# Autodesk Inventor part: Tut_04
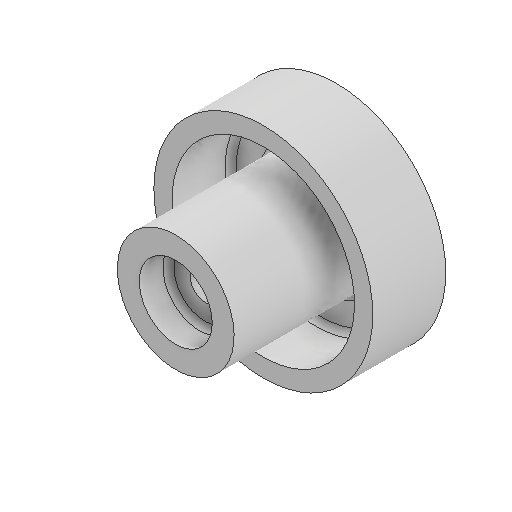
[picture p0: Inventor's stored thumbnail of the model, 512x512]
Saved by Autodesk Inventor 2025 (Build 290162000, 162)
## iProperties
Created: 2019-02
Part Number: Tut_04
Material: Generic
Document SubType Name: Modeling
Designer: LENOVO-CADCIM
Density: 1 g/cm^3
Appearance: Default
Author: LENOVO-CADCIM
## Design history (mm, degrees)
revolve "Revolution1" stored, may be unused: angle "d31" = 90 deg
body "Solid1"
sketch "Sketch1"
  geometry: L1 (0, 0)-(0, 22); L2 (0, 22)-(4, 22); L3 (4, 22)-(4, 36); L4 (4, 36)-(8.5, 36); L5 (10, 37.5)-(10, 44); L6 (10, 44)-(16, 44); L7 (16, 44)-(16, 5.5); L8 (17.5, 4)-(23.5, 4); L9 (25, 5.5)-(25, 20); L10 (25, 20)-(30, 20); L11 (30, 20)-(30, 0); L12 (30, 0)-(0, 0); A1 r 1.5 centre (8.5, 37.5) between (8.5, 36) and (10, 37.5); A2 r 1.5 centre (17.5, 5.5) between (16, 5.5) and (17.5, 4); A3 r 1.5 centre (23.5, 5.5) between (23.5, 4) and (25, 5.5); 4 further points
  constraints: 24 end point, 11 perpendicular, 6 point on circle, 6 point on line, 6 tangent, 3 centre point, 1 equal radius, 1 midpoint, 1 vertical
  dimensions: "d21" = 22 distance of L1.start L1.end; "d22" = 36 distance between parallel lines of L12 L4; "d23" = 44 distance between parallel lines of L12 L6; "d24" = 25 distance between parallel lines of L9 L1; "d25" = 30 distance from line of point (30, 10) L1; "d26" = 4 distance between parallel lines of L8 L12; "d27" = 4 distance between parallel lines of L1 L3; "d28" = 10 distance between parallel lines of L5 L1; "d29" = 16 distance between parallel lines of L7 L1; "d30" = 20 distance of L10.end L11.end; "d32" = 1.5 radius of A1; "d33" = 1.5 radius of A2 (derived)
